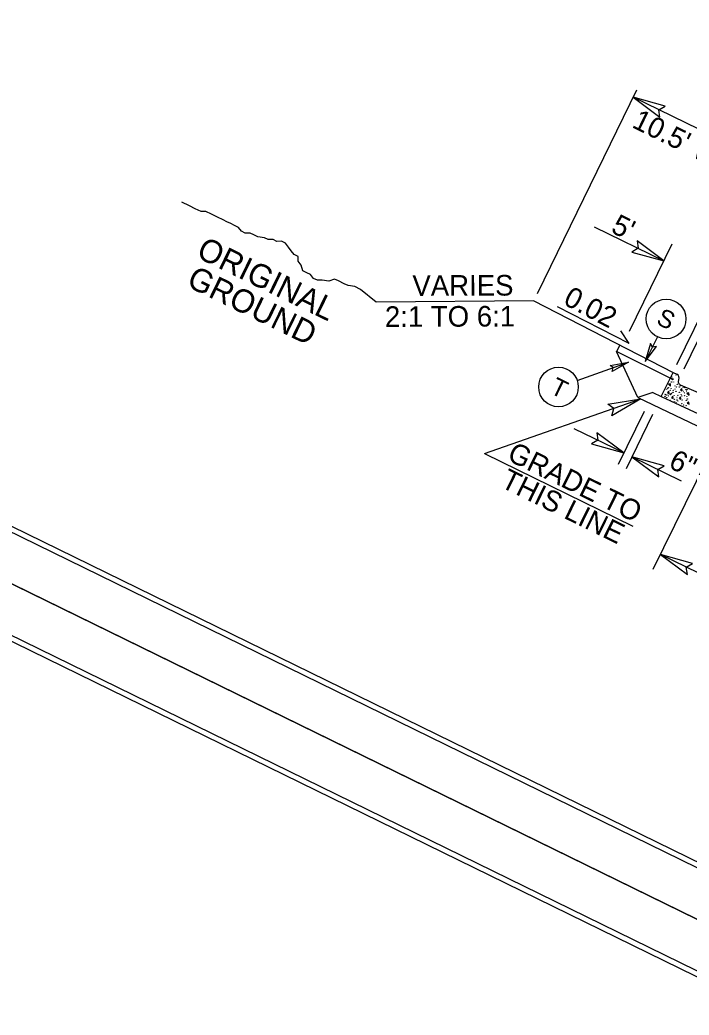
# Model space of a CAD drawing. Extents: x 1518247 to 1523638, y 635234 to 639927.
# Drawn here: x 1521242.6 to 1521566.4, y 638576.7 to 639057.9 of the extents above; entities that cross this region are included whole.
import ezdxf

# ---------------------------------------------------------------- set-up
doc = ezdxf.new("R2010")
doc.units = 0
for name, color, linetype in [('Default', 7, 'Continuous'), ('Prop Dimension', 7, 'Continuous'), ('Prop Shade Light', 7, 'Continuous'), ('Sheet Cutting Line CELL', 7, 'Continuous'), ('Sheet Plot Border Inside CELL', 7, 'Continuous'), ('Sheet Plot Border Outside CELL', 7, 'Continuous'), ('Sheet Typical CELL', 7, 'Continuous'), ('Typical Arrow Superelevation CELL', 7, 'Continuous'), ('Typical Berm CELL', 7, 'Continuous'), ('Typical Berm Information CELL', 7, 'Continuous'), ('Typical Curb CELL', 7, 'Continuous'), ('Typical Hinge Slope Arterial CELL', 7, 'Continuous'), ('Typical Hinge Slope Interstate CELL', 7, 'Continuous'), ('Typical ID Circle CELL', 7, 'Continuous'), ('Typical Pavement Slope CELL', 7, 'Continuous'), ('Typical Text General CELL', 7, 'Continuous'), ('Typical Text ID Circle CELL', 7, 'Continuous')]:
    doc.layers.add(name, color=color, linetype=linetype)

# ---------------------------------------------------------------- blocks, each defined once
blk = doc.blocks.new('TERMINATOR')
at = {"layer": 'Prop Shade Light'}
blk.add_lwpolyline([(-0.469, 0.081), (0, 0), (-0.471, -0.083), (-0.411, 0)], close=True, dxfattribs=at)

msp = doc.modelspace()

# ---------------------------------------------------------------- linework, layer by layer
at = {"layer": 'Default'}
for points in [[(1522438.02, 638198.63), (1520925.25, 638938.49), (1521408.53, 639926.64), (1522921.3, 639186.78)], [(1520441.97, 637950.34), (1521954.73, 637210.48), (1522438.02, 638198.63), (1520925.25, 638938.49)]]:
    msp.add_lwpolyline(points, close=True, dxfattribs=at)
at = {"layer": 'Prop Dimension'}
for p, q in [((1521493.05, 638925.73), (1521541.1, 639024.15)), ((1521610.99, 638985.59), (1521539.35, 639020.56)), ((1521563.96, 638889.26), (1521621.37, 639006.86)), ((1521520.49, 638957.94), (1521554.27, 638941.4)), ((1521537.65, 638907.49), (1521558.28, 638949.59)), ((1521560.46, 638891.25), (1521582.21, 638935.81)), ((1521467.39, 638848.35), (1521543.09, 638874.68)), ((1521544.62, 638868.64), (1521532.08, 638842.96)), ((1521548.7, 638867.09), (1521535.9, 638840.87)), ((1521534.82, 638848.57), (1521510.88, 638860.26)), ((1521467.39, 638848.35), (1521539.27, 638813.13)), ((1521562.73, 638834.94), (1521538.73, 638846.66)), ((1521549.01, 638792.36), (1521575.18, 638845.34)), ((1521918.24, 638620.97), (1521552.58, 638799.48))]:
    msp.add_line(p, q, dxfattribs=at)
at = {"layer": 'Prop Shade Light'}
for points in [[(1521547.76, 638901.4), (1521545.23, 638892.76), (1521550.57, 638900.09), (1521548.65, 638899.76)], [(1521528.2, 638890.87), (1521537.08, 638892.38), (1521529.19, 638887.92), (1521529.73, 638889.79)]]:
    msp.add_lwpolyline(points, close=True, dxfattribs=at)
at = {"layer": 'Sheet Cutting Line CELL'}
for p, q in [((1520925.25, 638938.49), (1522438.02, 638198.63)), ((1522438.02, 638198.63), (1520925.25, 638938.49))]:
    msp.add_line(p, q, dxfattribs=at)
at = {"layer": 'Sheet Plot Border Inside CELL'}
for points in [[(1522907.39, 639168.59), (1521410.35, 639900.76), (1520946.79, 638952.95), (1522443.84, 638220.77)], [(1522424.11, 638180.44), (1520927.06, 638912.61), (1520463.51, 637964.8), (1521960.55, 637232.62)]]:
    msp.add_lwpolyline(points, close=True, dxfattribs=at)
at = {"layer": 'Sheet Plot Border Outside CELL'}
for points in [[(1522921.3, 639186.78), (1521408.53, 639926.64), (1520925.25, 638938.49), (1522438.02, 638198.63)], [(1522438.02, 638198.63), (1520925.25, 638938.49), (1520441.97, 637950.34), (1521954.73, 637210.48)]]:
    msp.add_lwpolyline(points, close=True, dxfattribs=at)
at = {"layer": 'Sheet Typical CELL'}
msp.add_line((1521557.32, 638884.74), (1521531.34, 638897.54), dxfattribs=at)
for points in [[(1522895.04, 639171.79), (1521547.57, 639830.81), (1521086.25, 638887.58), (1522433.73, 638228.56)], [(1522411.76, 638183.64), (1521064.29, 638842.66), (1520602.97, 637899.43), (1521950.45, 637240.41)]]:
    msp.add_lwpolyline(points, close=True, dxfattribs=at)
at = {"layer": 'Typical Arrow Superelevation CELL'}
msp.add_line((1521537.36, 638901.4), (1521533.4, 638907.53), dxfattribs=at)
at = {"layer": 'Typical Berm CELL'}
msp.add_line((1521491.3, 638922.14), (1521558.66, 638887.5), dxfattribs=at)
at = {"layer": 'Typical Berm Information CELL'}
msp.add_line((1521537.36, 638901.4), (1521502.81, 638919.16), dxfattribs=at)
at = {"layer": 'Typical Curb CELL'}
for p, q in [((1521552.95, 638875.79), (1521558.66, 638887.5)), ((1521558.66, 638887.5), (1521560.53, 638886.59)), ((1521557.39, 638881.94), (1521556.39, 638881.76)), ((1521557.44, 638880.9), (1521557.39, 638881.94)), ((1521558.43, 638883.85), (1521557.6, 638884.66)), ((1521557.6, 638884.66), (1521558.86, 638884.44)), ((1521558.86, 638884.44), (1521558.43, 638883.85)), ((1521561.37, 638883.96), (1521561.41, 638884.03)), ((1521556.64, 638878.48), (1521556, 638877.78)), ((1521556, 638877.78), (1521556.84, 638877.32)), ((1521556.39, 638881.76), (1521557.44, 638880.9)), ((1521556.84, 638877.32), (1521556.64, 638878.48)), ((1521562.9, 638879.75), (1521562.26, 638879.05)), ((1521562.26, 638879.05), (1521563.1, 638878.59)), ((1521575.12, 638875.77), (1521562.32, 638881.37)), ((1521563.1, 638878.59), (1521562.9, 638879.75)), ((1521566.34, 638877.57), (1521565.34, 638877.39)), ((1521565.34, 638877.39), (1521566.39, 638876.53)), ((1521566.39, 638876.53), (1521566.34, 638877.57)), ((1521552.95, 638875.79), (1521571.04, 638867.41)), ((1521558.54, 638875.97), (1521557.89, 638875.28)), ((1521557.89, 638875.28), (1521558.74, 638874.81)), ((1521558.74, 638874.81), (1521558.54, 638875.97)), ((1521562.2, 638875.64), (1521561.56, 638874.94)), ((1521561.56, 638874.94), (1521562.4, 638874.48)), ((1521562.4, 638874.48), (1521562.2, 638875.64)), ((1521566.2, 638873.27), (1521565.56, 638872.57)), ((1521565.56, 638872.57), (1521566.4, 638872.11)), ((1521566.4, 638872.11), (1521566.2, 638873.27))]:
    msp.add_line(p, q, dxfattribs=at)
for centre in [(1521558.38, 638886.66), (1521557.84, 638882.88), (1521558.1, 638885.18), (1521558.88, 638882.82), (1521560.05, 638886.15), (1521560.82, 638882.13), (1521554.8, 638876.94), (1521555.48, 638879.2), (1521556.04, 638879.83), (1521556.37, 638880.16), (1521557.29, 638878.87), (1521557.49, 638877), (1521557.73, 638879.84), (1521557.94, 638877.33), (1521558.63, 638877.87), (1521558.78, 638878.78), (1521559.57, 638881.02), (1521559.59, 638879.39), (1521560.11, 638878.38), (1521560.37, 638880.38), (1521560.77, 638881.71), (1521561.6, 638876.99), (1521561.66, 638877.83), (1521561.74, 638880.47), (1521562.3, 638881.1), (1521563.55, 638880.14), (1521563.75, 638878.27), (1521564.28, 638877.61), (1521564.4, 638880.11), (1521564.89, 638879.14), (1521565.19, 638878.43), (1521565.41, 638879.19), (1521554.77, 638875.92), (1521555.4, 638876.55), (1521555.57, 638875.28), (1521555.97, 638876.6), (1521556.38, 638876.16), (1521557.3, 638874.05), (1521557.37, 638876.7), (1521559.19, 638876.37), (1521559.36, 638873.47), (1521559.39, 638874.5), (1521560.16, 638872.83), (1521560.52, 638875.36), (1521560.55, 638874.16), (1521560.96, 638873.71), (1521561.04, 638876.36), (1521562.57, 638876.78), (1521562.85, 638872.44), (1521562.85, 638876.03), (1521563.05, 638874.16), (1521564.04, 638873.12), (1521564.15, 638876.2), (1521564.19, 638875.03), (1521565.04, 638873.99), (1521565.32, 638875.79), (1521565.6, 638874.62), (1521563.65, 638871.79), (1521564.96, 638871.35)]:
    msp.add_circle(centre, 0.064, dxfattribs=at)
for centre, start, end in [((1521559.69, 638884.87), 333.9793, 63.9793), ((1521563.09, 638883.12), 153.9793, 246.3637)]:
    msp.add_arc(centre, 1.91, start, end, dxfattribs=at)
at = {"layer": 'Typical Hinge Slope Interstate CELL'}
for p, q in [((1521491.3, 638922.14), (1521415.08, 638921.42)), ((1521532.98, 638900.71), (1521531.34, 638897.54))]:
    msp.add_line(p, q, dxfattribs=at)
msp.add_lwpolyline([(1521415.08, 638921.42), (1521407.45, 638927.64), (1521404.65, 638929), (1521401.42, 638929.44), (1521399.56, 638930.34), (1521396.77, 638931.71), (1521394.91, 638932.61), (1521392.14, 638931.65), (1521388.9, 638932.09), (1521386.58, 638932.07), (1521384.72, 638932.97), (1521383.32, 638934.81), (1521381.46, 638935.72), (1521379.6, 638936.63), (1521378.65, 638939.39), (1521377.25, 638941.23), (1521377.22, 638943.55), (1521375.37, 638944.46), (1521373.96, 638946.29), (1521372.56, 638948.13), (1521371.15, 638949.97), (1521369.29, 638950.88), (1521366.98, 638950.85), (1521365.12, 638951.76), (1521362.81, 638951.73), (1521360.95, 638952.64), (1521357.71, 638953.08), (1521355.85, 638953.98), (1521353.99, 638954.89), (1521351.67, 638954.87), (1521349.82, 638955.77), (1521348.41, 638957.61), (1521346.55, 638958.52), (1521344.7, 638959.43), (1521342.84, 638960.34), (1521340.98, 638961.24), (1521338.19, 638962.61), (1521335.4, 638963.96), (1521332.61, 638965.33), (1521330.3, 638965.3), (1521327.51, 638966.66), (1521324.72, 638968.02), (1521321, 638969.84)], dxfattribs=at)
at = {"layer": 'Typical ID Circle CELL'}
for p, q in [((1521551.07, 638904.72), (1521545.23, 638892.76)), ((1521512.27, 638883.63), (1521537.08, 638892.38))]:
    msp.add_line(p, q, dxfattribs=at)
for centre in [(1521555.28, 638913.33), (1521503.23, 638880.44)]:
    msp.add_circle(centre, 9.59, dxfattribs=at)
at = {"layer": 'Typical Pavement Slope CELL'}
for p, q in [((1521541.69, 638875.33), (1521531.34, 638897.54)), ((1521548.86, 638877.8), (1521541.69, 638875.33)), ((1521548.86, 638877.8), (1521552.95, 638875.79)), ((1521541.69, 638875.33), (1521580.87, 638856.63))]:
    msp.add_line(p, q, dxfattribs=at)

# ---------------------------------------------------------------- block references
at = {"layer": 'Prop Dimension'}
for p, xscale, yscale, rotation in [((1521539.35, 639020.56), 33.82820784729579, -36.41552511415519, 153.97926941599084), ((1521554.27, 638941.4), 33.82820784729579, -36.41552511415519, -26.020730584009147), ((1521543.09, 638874.68), 33.82820784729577, 36.41552511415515, 19.577213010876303), ((1521534.82, 638848.57), 33.82820784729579, -36.41552511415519, -26.020730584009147), ((1521538.73, 638846.66), 33.82820784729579, -36.41552511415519, 153.97926941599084), ((1521552.58, 638799.48), 33.82820784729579, -36.41552511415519, 153.97926941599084)]:
    msp.add_blockref('TERMINATOR', p, dxfattribs=dict(at, xscale=xscale, yscale=yscale, rotation=rotation))

# ---------------------------------------------------------------- texts
for s, rotation, p in [("10.5' W/GR", 333.8962, (1521538.29, 639006.22)), ("5'", 333.9793, (1521528.08, 638955.46)), ('6"', 333.9793, (1521555.92, 638841.71))]:
    msp.add_text(s, height=9.969, rotation=rotation, dxfattribs=at).set_placement(p)
at = {"layer": 'Typical Berm Information CELL'}
msp.add_text('0.02', height=9.969, rotation=332.1708, dxfattribs=at).set_placement((1521505.02, 638920.72))
at = {"layer": 'Typical Hinge Slope Arterial CELL'}
for s, p in [('VARIES', (1521432.57, 638924.49)), ('2:1 TO 6:1', (1521419.26, 638909.49))]:
    msp.add_text(s, height=9.969, rotation=0.2071, dxfattribs=at).set_placement(p)
at = {"layer": 'Typical Hinge Slope Interstate CELL'}
for s, p in [('ORIGINAL', (1521327.47, 638943.43)), ('GROUND', (1521322.74, 638929.39))]:
    msp.add_text(s, height=11.211, rotation=334.0511, dxfattribs=at).set_placement(p)
at = {"layer": 'Typical Text General CELL'}
for s, p in [('GRADE TO', (1521477.83, 638845.34)), ('THIS LINE', (1521474.68, 638832.33))]:
    msp.add_text(s, height=9.969, rotation=333.8962, dxfattribs=at).set_placement(p)
at = {"layer": 'Typical Text ID Circle CELL'}
for s, p in [('S', (1521550, 638911.18)), ('T', (1521498.67, 638877.64))]:
    msp.add_text(s, height=8.58, rotation=333.9793, dxfattribs=at).set_placement(p)

doc.saveas('drawing.dxf')
